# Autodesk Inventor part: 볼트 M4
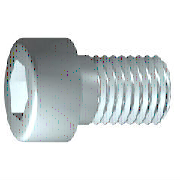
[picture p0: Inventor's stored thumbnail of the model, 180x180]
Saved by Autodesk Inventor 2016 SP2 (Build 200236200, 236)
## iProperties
IsCustomPart: 0
Created: 2016-04
Part Number: 볼트 M4
Material: 강철, 연강
Description: 6각머리 태핑 나사
Document SubType Name: Modeling
Standard: KS B 1003
Designer: mdu
Standards Organization: KS
Language: ko-KR
Size Designation: M 4 x 10
Categories: <MemberInstance><Categories><Category DisplayName="조임쇠" InternalName="e4da775c-781d-43d5-af7c-5136215cf5a6" Mnemonic="FSTN"><Category DisplayName="볼트" InternalN
Density: 7.86 g/cm^3
Mass: 2.0371 g
Surface Area: 3.0572 cm^2
Volume: 0.259174 cm^3
Appearance: 금속 1800F 열
Author: mdu
Revision Number: 1
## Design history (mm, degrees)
sketch "스케치1"
  geometry: L1 (-1, 0)-(10, 0); L2 (10, 0)-(10, 2); L3 (10, 2)-(1.75, 2); L4 (1.75, 2)-(1.32, 2); L5 (1.32, 2)-(0, 2); L6 (0, 2)-(0, 3.5); L7 (0, 3.5)-(-4, 3.5); L8 (-4, 3.5)-(-4, 1.732); L9 (-4, 1.732)-(-2, 1.732); L10 (-2, 1.732)-(-1, 0); L11 (-6.8, 0)-(12.8, 0) reference; L12 (0, -0.7)-(0, 4.2) reference; L13 (1.75, 2)-(0, 2)
  constraints: 22 end point, 6 parallel, 2 collinear, 2 perpendicular, 1 horizontal, 1 point on line
  dimensions: "d1" = 8.25 distance from line of L3.end L2 (= GEL); "d2" = 0.42952 distance of L4.end L3.end (computed from GAL); "d3" = 4 distance between parallel lines of L8 L6 (= KOH); "d4" = 2 distance of L8.end L9.end (= INTI); "d5" = 60 deg angle of L10 L1; "d6" = 4 diameter of L3 L1 (= GD); "d7" = 4 diameter of L5 L1 (= BDM); "d8" = 3.4641 diameter of L9 L1 (= 1.1547 x SW); "d9" = 7 diameter of L7 L1 (= KOD); "d26" = 10 distance between parallel lines of L12 L2 (= NLG)
revolve "본체" sketch "스케치1" stored, may be unused: angle "d10" = 90 deg
sketch "스케치2"
  geometry: L1 (0, -4.9)-(0, 4.9) reference; L2 (-4.9, 0)-(4.9, 0) reference; L3 (1.732, 0)-(0.866, -1.5); L4 (0.866, -1.5)-(-0.866, -1.5); L5 (-0.866, -1.5)-(-1.732, 0); L6 (-1.732, 0)-(-0.866, 1.5); L7 (-0.866, 1.5)-(0.866, 1.5); L8 (0.866, 1.5)-(1.732, 0); 2 further points
  constraints: 12 end point, 1 coincident, 1 horizontal alignment, 1 point on line, 12 other
extrude "슬롯" join sketch "스케치2" stored distance "d11" = 10; taper "d12" = 0 deg
workplane "Work Plane1"
fillet "Fillet2" dims "d30" = 0.1 (= R)
body "Solid1"
fillet "모깎기1" dims "d17" = 0.4 (= RR)
feature "스레드" dims "d13" = 8.25 (= GEL), "d14" = 0
chamfer "모따기1" distance "d15" = 0.42941 (= -0.5 x SPD + 0.5 x GD); stored, may be unused: second distance "d16" = 0.42941 (= GUL), angle "d27" = 45 deg
other parameters: "GD" = 4 (= NND) [user parameter; used in 2 equation terms], "NLG" = 10 [user parameter; used in 1 equation term], "GEL" = 8.25 [user parameter; used in 2 equation terms], "KOD" = 7 [user parameter; used in 1 equation term], "KOH" = 4 [user parameter; used in 1 equation term], "INTI" = 2 [user parameter; used in 1 equation term], "GAL" = 0.42941 (= 0.61345 x PTC) [user parameter; used in 1 equation term], "GUL" = 0.42941 (= 0.61345 x PTC) [user parameter; used in 1 equation term], "BDM" = 4 (= NND) [user parameter; used in 1 equation term], "SW" = 3 [user parameter; used in 2 equation terms], "RR" = 0.4 [user parameter; used in 1 equation term], "SPD" = 3.14117 (= NND - 1.2269 x PTC) [user parameter; used in 1 equation term], "d19" = 0, "d28" = 0, "d29" = 0, "R" = 0.1 [user parameter; used in 1 equation term], "PHH" = 0.2 [user parameter], "GD1" = 3.14117 (= THREADDIA - 1.2269 x PTC) [user parameter], "THREADDIA" = 4 [user parameter; used in 1 equation term], "FAWI" = 45 deg [user parameter], "TPU" = 14.28571 (computed from PTC) [user parameter], "PTC" = 0.7 [user parameter; used in 5 equation terms], "NND" = 4 [user parameter; used in 3 equation terms], "TOA" = 30 deg [user parameter], "E0" = 3.465 (= 1.155 x SW) [user parameter]
